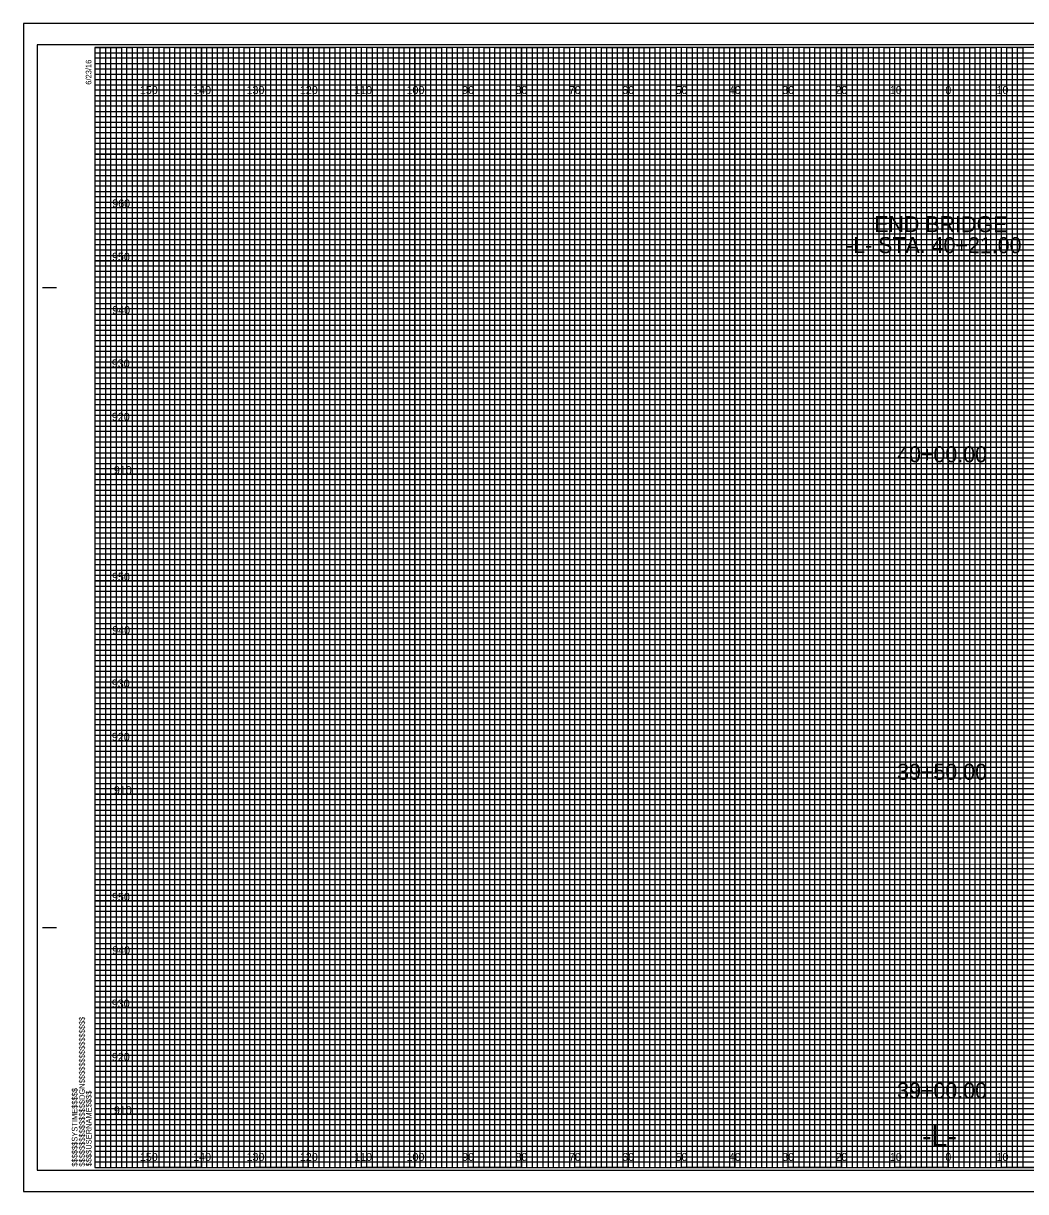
# Model space of a CAD drawing. Extents: x -13 to 323, y -4 to 3074.
# Drawn here: x -13.4 to 174.5, y 1315.5 to 1534.5 of the extents above; entities that cross this region are included whole.
import ezdxf

# ---------------------------------------------------------------- set-up
doc = ezdxf.new("R2010")
doc.units = 0
for name, color, linetype in [('Prop XS Alignment Label', 7, 'Continuous'), ('Prop XS Elevation Labels', 7, 'Continuous'), ('Prop XS Offset Labels', 7, 'Continuous'), ('Prop XS SE Text', 7, 'Continuous'), ('Prop XS Station Labels', 7, 'Continuous'), ('Sheet Cross Section CELL', 7, 'Continuous'), ('Sheet Cross Section Grid Major CELL', 7, 'Continuous'), ('Sheet Cross Section Grid Middle CELL', 7, 'Continuous'), ('Sheet Cross Section Grid Minor 1 CELL', 7, 'Continuous'), ('Sheet Cross Section Grid Minor 2 CELL', 7, 'Continuous'), ('Sheet Cutting Line CELL', 7, 'Continuous'), ('Sheet DOT Grid CELL', 7, 'Continuous'), ('Sheet Plot Border Inside CELL', 7, 'Continuous'), ('Sheet Plot Border Outside CELL', 7, 'Continuous')]:
    doc.layers.add(name, color=color, linetype=linetype)

msp = doc.modelspace()

# ---------------------------------------------------------------- linework, layer by layer
at = {"layer": 'Sheet Cross Section CELL'}
for p, q in [((-9.8, 1485), (-7.3, 1485)), ((-9.7, 1485), (-7.2, 1485)), ((-9.8, 1365), (-7.3, 1365)), ((-9.7, 1365), (-7.2, 1365)), ((0, 1320), (0, 1320)), ((0, 1320), (0, 1320)), ((0, 1320), (0, 1320)), ((0, 1320), (0, 1320)), ((0, 1320), (0, 1320)), ((0, 1320), (0, 1320)), ((0, 1320), (0, 1320))]:
    msp.add_line(p, q, dxfattribs=at)
msp.add_lwpolyline([(320, 1530), (0, 1530), (0, 1320), (320, 1320)], close=True, dxfattribs=at)
at = {"layer": 'Sheet Cross Section Grid Major CELL'}
for p, q in [((10, 1530), (0, 1530)), ((10, 1320), (10, 1530)), ((30, 1530), (20, 1530)), ((20, 1530), (20, 1320)), ((30, 1320), (30, 1530)), ((50, 1530), (40, 1530)), ((40, 1530), (40, 1320)), ((50, 1320), (50, 1530)), ((70, 1530), (60, 1530)), ((60, 1530), (60, 1320)), ((70, 1320), (70, 1530)), ((90, 1530), (80, 1530)), ((80, 1530), (80, 1320)), ((90, 1320), (90, 1530)), ((110, 1530), (100, 1530)), ((100, 1530), (100, 1320)), ((110, 1320), (110, 1530)), ((130, 1530), (120, 1530)), ((120, 1530), (120, 1320)), ((130, 1320), (130, 1530)), ((150, 1530), (140, 1530)), ((140, 1530), (140, 1320)), ((150, 1320), (150, 1530)), ((170, 1530), (160, 1530)), ((160, 1530), (160, 1320)), ((170, 1320), (170, 1530)), ((20, 1320), (10, 1320)), ((40, 1320), (30, 1320)), ((60, 1320), (50, 1320)), ((80, 1320), (70, 1320)), ((100, 1320), (90, 1320)), ((120, 1320), (110, 1320)), ((140, 1320), (130, 1320)), ((160, 1320), (150, 1320)), ((180, 1320), (170, 1320))]:
    msp.add_line(p, q, dxfattribs=at)
for points in [[(0, 1520), (320, 1520), (320, 1510), (0, 1510)], [(0, 1500), (320, 1500), (320, 1490), (0, 1490)], [(0, 1480), (320, 1480), (320, 1470), (0, 1470)], [(0, 1460), (320, 1460), (320, 1450), (0, 1450)], [(0, 1440), (320, 1440), (320, 1430), (0, 1430)], [(0, 1420), (320, 1420), (320, 1410), (0, 1410)], [(0, 1400), (320, 1400), (320, 1390), (0, 1390)], [(0, 1380), (320, 1380), (320, 1370), (0, 1370)], [(0, 1360), (320, 1360), (320, 1350), (0, 1350)], [(0, 1340), (320, 1340), (320, 1330), (0, 1330)]]:
    msp.add_lwpolyline(points, dxfattribs=at)
at = {"layer": 'Sheet Cross Section Grid Middle CELL'}
for points in [[(0, 1530), (5, 1530), (5, 1320), (15, 1320), (15, 1530), (25, 1530), (25, 1320), (35, 1320), (35, 1530), (45, 1530), (45, 1320), (55, 1320), (55, 1530), (65, 1530), (65, 1320), (75, 1320), (75, 1530), (85, 1530), (85, 1320), (95, 1320), (95, 1530), (105, 1530), (105, 1320), (115, 1320), (115, 1530), (125, 1530), (125, 1320), (135, 1320), (135, 1530), (145, 1530), (145, 1320), (155, 1320), (155, 1530), (165, 1530), (165, 1320), (175, 1320)], [(0, 1525), (275, 1525)], [(0, 1505), (320, 1505), (320, 1515), (0, 1515)], [(0, 1485), (320, 1485), (320, 1495), (0, 1495)], [(0, 1465), (320, 1465), (320, 1475), (0, 1475)], [(0, 1445), (320, 1445), (320, 1455), (0, 1455)], [(0, 1425), (320, 1425), (320, 1435), (0, 1435)], [(0, 1405), (320, 1405), (320, 1415), (0, 1415)], [(0, 1385), (320, 1385), (320, 1395), (0, 1395)], [(0, 1365), (320, 1365), (320, 1375), (0, 1375)], [(0, 1345), (320, 1345), (320, 1355), (0, 1355)], [(0, 1325), (320, 1325), (320, 1335), (0, 1335)]]:
    msp.add_lwpolyline(points, dxfattribs=at)
at = {"layer": 'Sheet Cross Section Grid Minor 1 CELL'}
for p, q in [((0, 1529), (260, 1529)), ((260, 1527.98), (0, 1527.98)), ((0, 1527.98), (0, 1527)), ((0, 1527), (260, 1527)), ((260, 1525.89), (0, 1525.89)), ((0, 1525.89), (0, 1524)), ((0, 1524), (320, 1524))]:
    msp.add_line(p, q, dxfattribs=at)
for points in [[(0, 1523), (270, 1523), (320, 1523), (320, 1522), (0, 1522)], [(0, 1521), (320, 1521), (320, 1519), (0, 1519)], [(0, 1518), (320, 1518), (320, 1517), (0, 1516.98)], [(0, 1516), (320, 1516), (320, 1514), (0, 1514)], [(0, 1513), (320, 1513), (320, 1512), (0, 1512)], [(0, 1511), (320, 1511), (320, 1509), (0, 1509)], [(0, 1508), (320, 1508), (320, 1507), (0, 1507)], [(0, 1506), (320, 1506), (320, 1504), (0, 1504)], [(0, 1503), (320, 1503), (320, 1502), (0, 1502)], [(0, 1501), (320, 1501), (320, 1499), (0, 1499)], [(0, 1498), (320, 1498), (320, 1497), (0, 1497)], [(0, 1496), (320, 1496), (320, 1493.95), (320, 1493), (320, 1492), (0, 1492)], [(0, 1494), (320, 1494), (320, 1493), (0, 1493)], [(0, 1491), (320, 1491), (320, 1489), (0, 1489.03)], [(0, 1489.03), (320, 1489), (320, 1488), (0, 1488)], [(0, 1487), (320, 1487), (320, 1486), (0, 1486)], [(0, 1484), (320, 1484), (320, 1483), (0, 1483)], [(0, 1482), (320, 1482), (320, 1481), (0, 1481)], [(-0.07, 1478.89), (320, 1478.89), (320, 1477.88), (-0.07, 1477.88)], [(0, 1477), (320, 1477), (320, 1476), (0, 1476)], [(0, 1474), (320, 1474), (320, 1473), (0, 1473)], [(0, 1472), (320, 1472), (320, 1471), (0, 1471)], [(0, 1469), (320, 1469), (320, 1468), (0, 1468)], [(0, 1467), (320, 1467), (320, 1466), (0, 1466)], [(0, 1464), (320, 1464), (320, 1463), (0, 1463)], [(0, 1462), (320, 1462), (320, 1461), (0, 1461)], [(0, 1459), (320, 1459), (319.99, 1457.98), (0, 1458)], [(0, 1457), (320, 1457), (320, 1456), (0, 1456)], [(0, 1454), (320, 1454), (320, 1453), (0, 1453)], [(0, 1452), (320, 1452), (320, 1451), (0, 1451)], [(0, 1449), (320, 1449), (320, 1448), (0, 1448)], [(0, 1447), (320, 1447), (320, 1446), (0, 1446)], [(0, 1444), (320, 1444), (320, 1443), (0, 1443)], [(0, 1442), (320, 1442), (320, 1441), (0, 1441)], [(0, 1439), (320, 1439), (320, 1438), (0, 1438)], [(0, 1436.99), (320.07, 1436.91), (320, 1436), (0, 1436)], [(0, 1434), (320, 1434), (320, 1433), (0, 1433)], [(0, 1432), (320, 1432), (320, 1431), (0, 1431)], [(0, 1429), (320, 1429), (320, 1428), (0, 1428)], [(0, 1427), (320, 1427), (320, 1426), (0, 1426)], [(0, 1424), (320, 1424), (320, 1423), (0, 1423)], [(0, 1422), (320, 1422), (320, 1421), (0, 1421)], [(0, 1419), (320, 1419), (320, 1418), (0, 1418)], [(0, 1417), (320, 1417), (320, 1416), (0, 1416)], [(0, 1414), (320, 1414), (320, 1413), (0, 1413)], [(0, 1412), (320, 1412), (320, 1411), (0, 1411)], [(0, 1409), (320, 1409), (320, 1408), (0, 1408)], [(0, 1407), (320, 1407), (320, 1406), (0, 1406)], [(0, 1404), (320, 1404), (320, 1403), (0, 1403)], [(0, 1402), (320, 1402), (320, 1401), (0, 1401)], [(0, 1399), (320, 1399), (319.99, 1397.98), (0, 1398)], [(0, 1397), (320, 1397), (320, 1396), (0, 1396)], [(0, 1394), (320, 1394), (320, 1393), (0, 1393)], [(0, 1392), (320, 1392), (320, 1391), (0, 1391)], [(0, 1389), (320, 1389), (320, 1388), (0, 1388)], [(0, 1387), (320, 1387), (320, 1386), (0, 1386)], [(0, 1384), (320, 1384), (320, 1383), (0, 1383)], [(0, 1382), (320, 1382), (320, 1381), (0, 1381)], [(0, 1379), (320, 1379), (320, 1378), (0, 1378)], [(0, 1376.99), (320.07, 1376.91), (320, 1376), (0, 1376)], [(0, 1374), (320, 1374), (320, 1373), (0, 1373)], [(0, 1372), (320, 1372), (320, 1371), (0, 1371)], [(0, 1369), (320, 1369), (320, 1368), (0, 1368)], [(0, 1367), (320, 1367), (320, 1366), (0, 1366)], [(0, 1364), (320, 1364), (320, 1363), (0, 1363)], [(0, 1362), (320, 1362), (320, 1361), (0, 1361)], [(0, 1359), (320, 1359), (320, 1358), (0, 1358)], [(0, 1357), (320, 1357), (320, 1356), (0, 1356)], [(0, 1354), (320, 1354), (320, 1353), (0, 1353)], [(0, 1352), (320, 1352), (320, 1351), (0, 1351)], [(0, 1349), (320, 1349), (320, 1348), (0, 1348)], [(0, 1347), (320, 1347), (320, 1346), (0, 1346)], [(0, 1344), (320, 1344), (320, 1343), (0, 1343)], [(0, 1342), (320, 1342), (320, 1341), (0, 1341)], [(0, 1339), (320, 1339), (320, 1338), (0, 1338)], [(0, 1337), (320, 1337), (320, 1336), (0, 1336)], [(0, 1334), (320, 1334), (320, 1333), (0, 1333)], [(0, 1332), (320, 1332), (320, 1331), (0, 1331)], [(0, 1329), (320, 1329), (320, 1328), (0, 1328)], [(0, 1327), (320, 1327), (320, 1326), (0, 1326)], [(0, 1324), (320, 1324), (320, 1323), (0, 1323)], [(0, 1322), (320, 1322), (320, 1321), (0, 1321)]]:
    msp.add_lwpolyline(points, dxfattribs=at)
at = {"layer": 'Sheet Cross Section Grid Minor 2 CELL'}
for points in [[(0, 1320), (1, 1320), (1, 1530), (2, 1530), (2, 1320)], [(2, 1320), (3, 1320), (3, 1530), (4, 1530), (4, 1320)], [(5, 1320), (6, 1320), (6, 1530), (7, 1530), (7, 1320)], [(7, 1320), (8, 1320), (8, 1530), (9, 1530), (9, 1320)], [(10, 1320), (11, 1320), (11, 1530), (12, 1530), (12, 1320)], [(12, 1320), (13, 1320), (13, 1530), (14, 1530), (14, 1320)], [(15, 1320), (16, 1320), (16, 1530), (17, 1530), (17, 1320)], [(17, 1320), (18, 1320), (18, 1530), (19, 1530), (19, 1320)], [(20, 1320), (21, 1320), (21, 1530), (22, 1530), (22, 1320)], [(22, 1320), (23, 1320), (23, 1530), (24, 1530), (24, 1320)], [(25, 1320), (26, 1320), (26, 1530), (27, 1530), (27, 1320)], [(27, 1320), (28, 1320), (28, 1530), (29, 1530), (29, 1320)], [(30, 1320), (31, 1320), (31, 1530), (32, 1530), (32, 1320)], [(32, 1320), (33, 1320), (33, 1530), (34, 1530), (34, 1320)], [(35, 1320), (36, 1320), (36, 1530), (37, 1530), (37, 1320)], [(37, 1320), (38, 1320), (38, 1530), (39, 1530), (39, 1320)], [(40, 1320), (41, 1320), (41, 1530), (42, 1530), (42, 1320)], [(42, 1320), (43, 1320), (43, 1530), (44, 1530), (44, 1320)], [(45, 1320), (46, 1320), (46, 1530), (47, 1530), (47, 1320)], [(47, 1320), (48, 1320), (48, 1530), (49, 1530), (49, 1320)], [(50, 1320), (51, 1320), (51, 1530), (52, 1530), (52, 1320)], [(52, 1320), (53, 1320), (53, 1530), (54, 1530), (54, 1320)], [(55, 1320), (56, 1320), (56, 1530), (57, 1530), (57, 1320)], [(57, 1320), (58, 1320), (58, 1530), (59, 1530), (59, 1320)], [(60, 1320), (61, 1320), (61, 1530), (62, 1530), (62, 1320)], [(62, 1320), (63, 1320), (63, 1530), (64, 1530), (64, 1320)], [(65, 1320), (66, 1320), (66, 1530), (67, 1530), (67, 1320)], [(67, 1320), (68, 1320), (68, 1530), (69, 1530), (69, 1320)], [(70, 1320), (71, 1320), (71, 1530), (72, 1530), (72, 1320)], [(72, 1320), (73, 1320), (73, 1530), (74, 1530), (74, 1320)], [(75, 1320), (76, 1320), (76, 1530), (77, 1530), (77, 1320)], [(77, 1320), (78, 1320), (78, 1530), (79, 1530), (79, 1320)], [(80, 1320), (81, 1320), (81, 1530), (82, 1530), (82, 1320)], [(82, 1320), (83, 1320), (83, 1530), (84, 1530), (84, 1320)], [(85, 1320), (86, 1320), (86, 1530), (87, 1530), (87, 1320)], [(87, 1320), (88, 1320), (88, 1530), (89, 1530), (89, 1320)], [(90, 1320), (91, 1320), (91, 1530), (92, 1530), (92, 1320)], [(92, 1320), (93, 1320), (93, 1530), (94, 1530), (94, 1320)], [(95, 1320), (96, 1320), (96, 1530), (97, 1530), (97, 1320)], [(97, 1320), (98, 1320), (98, 1530), (99, 1530), (99, 1320)], [(100, 1320), (101, 1320), (101, 1530), (102, 1530), (102, 1320)], [(102, 1320), (103, 1320), (103, 1530), (104, 1530), (104, 1320)], [(105, 1320), (106, 1320), (106, 1530), (107, 1530), (107, 1320)], [(107, 1320), (108, 1320), (108, 1530), (109, 1530), (109, 1320)], [(110, 1320), (111, 1320), (111, 1530), (112, 1530), (112, 1320)], [(112, 1320), (113, 1320), (113, 1530), (114, 1530), (114, 1320)], [(115, 1320), (116, 1320), (116, 1530), (117, 1530), (117, 1320)], [(117, 1320), (118, 1320), (118, 1530), (119, 1530), (119, 1320)], [(120, 1320), (121, 1320), (121, 1530), (122, 1530), (122, 1320)], [(122, 1320), (123, 1320), (123, 1530), (124, 1530), (124, 1320)], [(125, 1320), (126, 1320), (126, 1530), (127, 1530), (127, 1320)], [(127, 1320), (128, 1320), (128, 1530), (129, 1530), (129, 1320)], [(130, 1320), (131, 1320), (131, 1530), (132, 1530), (132, 1320)], [(132, 1320), (133, 1320), (133, 1530), (134, 1530), (134, 1320)], [(135, 1320), (136, 1320), (136, 1530), (137, 1530), (137, 1320)], [(137, 1320), (138, 1320), (138, 1530), (139, 1530), (139, 1320)], [(140, 1320), (141, 1320), (141, 1530), (142, 1530), (142, 1320)], [(142, 1320), (143, 1320), (143, 1530), (144, 1530), (144, 1320)], [(145, 1320), (146, 1320), (146, 1530), (147, 1530), (147, 1320)], [(147, 1320), (148, 1320), (148, 1530), (149, 1530), (149, 1320)], [(150, 1320), (151, 1320), (151, 1530), (152, 1530), (152, 1320)], [(152, 1320), (153, 1320), (153, 1530), (154, 1530), (154, 1320)], [(155, 1320), (156, 1320), (156, 1530), (157, 1530), (157, 1320)], [(157, 1320), (158, 1320), (158, 1530), (159, 1530), (159, 1320)], [(160, 1320), (161, 1320), (161, 1530), (162, 1530), (162, 1320)], [(162, 1320), (163, 1320), (163, 1530), (164, 1530), (164, 1320)], [(165, 1320), (166, 1320), (166, 1530), (167, 1530), (167, 1320)], [(167, 1320), (168, 1320), (168, 1530), (169, 1530), (169, 1320)], [(170, 1320), (171, 1320), (171, 1530), (172, 1530), (172, 1320)], [(172, 1320), (173, 1320), (173, 1530), (174, 1530), (174, 1320)]]:
    msp.add_lwpolyline(points, dxfattribs=at)
at = {"layer": 'Sheet Cutting Line CELL'}
for p, q in [((323.3, 1534.5), (-13.4, 1534.5)), ((-13.4, 1534.5), (-13.4, 1315.5)), ((-13.4, 1315.5), (323.3, 1315.5))]:
    msp.add_line(p, q, dxfattribs=at)
at = {"layer": 'Sheet DOT Grid CELL'}
for p, q in [((10, 1320), (10, 1530)), ((20, 1320), (20, 1530)), ((30, 1320), (30, 1530)), ((40, 1320), (40, 1530)), ((50, 1320), (50, 1530)), ((60, 1320), (60, 1530)), ((70, 1320), (70, 1530)), ((80, 1320), (80, 1530)), ((90, 1320), (90, 1530)), ((100, 1320), (100, 1530)), ((110, 1320), (110, 1530)), ((120, 1320), (120, 1530)), ((130, 1320), (130, 1530)), ((140, 1320), (140, 1530)), ((150, 1320), (150, 1530)), ((160, 1320), (160, 1530)), ((170, 1320), (170, 1530)), ((0, 1520), (320, 1520)), ((0, 1510), (320, 1510)), ((0, 1500), (320, 1500)), ((0, 1490), (320, 1490)), ((0, 1480), (320, 1480)), ((0, 1470), (320, 1470)), ((0, 1460), (320, 1460)), ((0, 1450), (320, 1450)), ((0, 1440), (320, 1440)), ((0, 1430), (320, 1430)), ((0, 1420), (320, 1420)), ((0, 1410), (320, 1410)), ((0, 1400), (320, 1400)), ((0, 1390), (320, 1390)), ((0, 1380), (320, 1380)), ((0, 1370), (320, 1370)), ((0, 1360), (320, 1360)), ((0, 1350), (320, 1350)), ((0, 1340), (320, 1340)), ((0, 1330), (320, 1330))]:
    msp.add_line(p, q, dxfattribs=at)
at = {"layer": 'Sheet Plot Border Inside CELL'}
msp.add_lwpolyline([(-10.8, 1319.5), (322.4, 1319.5), (322.4, 1530.5), (-10.8, 1530.5)], close=True, dxfattribs=at)
at = {"layer": 'Sheet Plot Border Outside CELL'}
msp.add_lwpolyline([(-13.4, 1315.5), (323.3, 1315.5), (323.3, 1534.5), (-13.4, 1534.5)], close=True, dxfattribs=at)

# ---------------------------------------------------------------- texts
at = {"layer": 'Prop XS Alignment Label'}
msp.add_text('-L-', height=4, dxfattribs=at).set_placement((155.06, 1324))
at = {"layer": 'Prop XS Elevation Labels'}
for s, p in [('960', (3.26, 1500)), ('950', (3.22, 1490)), ('940', (3.26, 1480)), ('930', (3.18, 1470)), ('920', (3.19, 1460)), ('910', (3.57, 1450)), ('950', (3.22, 1430)), ('940', (3.26, 1420)), ('930', (3.18, 1410)), ('920', (3.19, 1400)), ('910', (3.57, 1390)), ('950', (3.22, 1370)), ('940', (3.26, 1360)), ('930', (3.18, 1350)), ('920', (3.19, 1340)), ('910', (3.57, 1330))]:
    msp.add_text(s, height=1.5, dxfattribs=at).set_placement(p)
at = {"layer": 'Prop XS Offset Labels'}
for s, p in [('150', (8.44, 1521.25)), ('140', (18.44, 1521.25)), ('130', (28.44, 1521.25)), ('120', (38.44, 1521.25)), ('110', (48.62, 1521.25)), ('100', (58.44, 1521.25)), ('90', (68.86, 1521.25)), ('80', (78.86, 1521.25)), ('70', (88.86, 1521.25)), ('60', (98.86, 1521.25)), ('50', (108.86, 1521.25)), ('40', (118.86, 1521.25)), ('30', (128.86, 1521.25)), ('20', (138.86, 1521.25)), ('10', (149.04, 1521.25)), ('0', (159.45, 1521.25)), ('0', (159.45, 1521.25)), ('10', (169.04, 1521.25)), ('150', (8.44, 1321.25)), ('140', (18.44, 1321.25)), ('130', (28.44, 1321.25)), ('120', (38.44, 1321.25)), ('110', (48.62, 1321.25)), ('100', (58.44, 1321.25)), ('90', (68.86, 1321.25)), ('80', (78.86, 1321.25)), ('70', (88.86, 1321.25)), ('60', (98.86, 1321.25)), ('50', (108.86, 1321.25)), ('40', (118.86, 1321.25)), ('30', (128.86, 1321.25)), ('20', (138.86, 1321.25)), ('10', (149.04, 1321.25)), ('0', (159.45, 1321.25)), ('0', (159.45, 1321.25)), ('10', (169.04, 1321.25))]:
    msp.add_text(s, height=1.5, dxfattribs=at).set_placement(p)
at = {"layer": 'Prop XS SE Text'}
for s, p in [('END BRIDGE', (146.12, 1495.37)), ('-L- STA. 40+21.00', (140.83, 1491.44))]:
    msp.add_text(s, height=3, rotation=359.9573, dxfattribs=at).set_placement(p)
at = {"layer": 'Prop XS Station Labels'}
for s, p in [('40+00.00', (150.41, 1452.22)), ('39+50.00', (150.41, 1392.71)), ('39+00.00', (150.41, 1332.94))]:
    msp.add_text(s, height=3, dxfattribs=at).set_placement(p)
at = {"layer": 'Sheet Cross Section CELL'}
for s, p in [('6/23/16', (-0.65, 1523)), ('$$$$$$$$$$$$$$$$DGN$$$$$$$$$$$$$$$$', (-1.88, 1320.18)), ('$$$$$$SYSTIME$$$$$', (-3.26, 1320.18)), ('$$$$USERNAME$$$$', (-0.62, 1320.23))]:
    msp.add_text(s, height=1.05, rotation=90, dxfattribs=at).set_placement(p)

doc.saveas('drawing.dxf')
